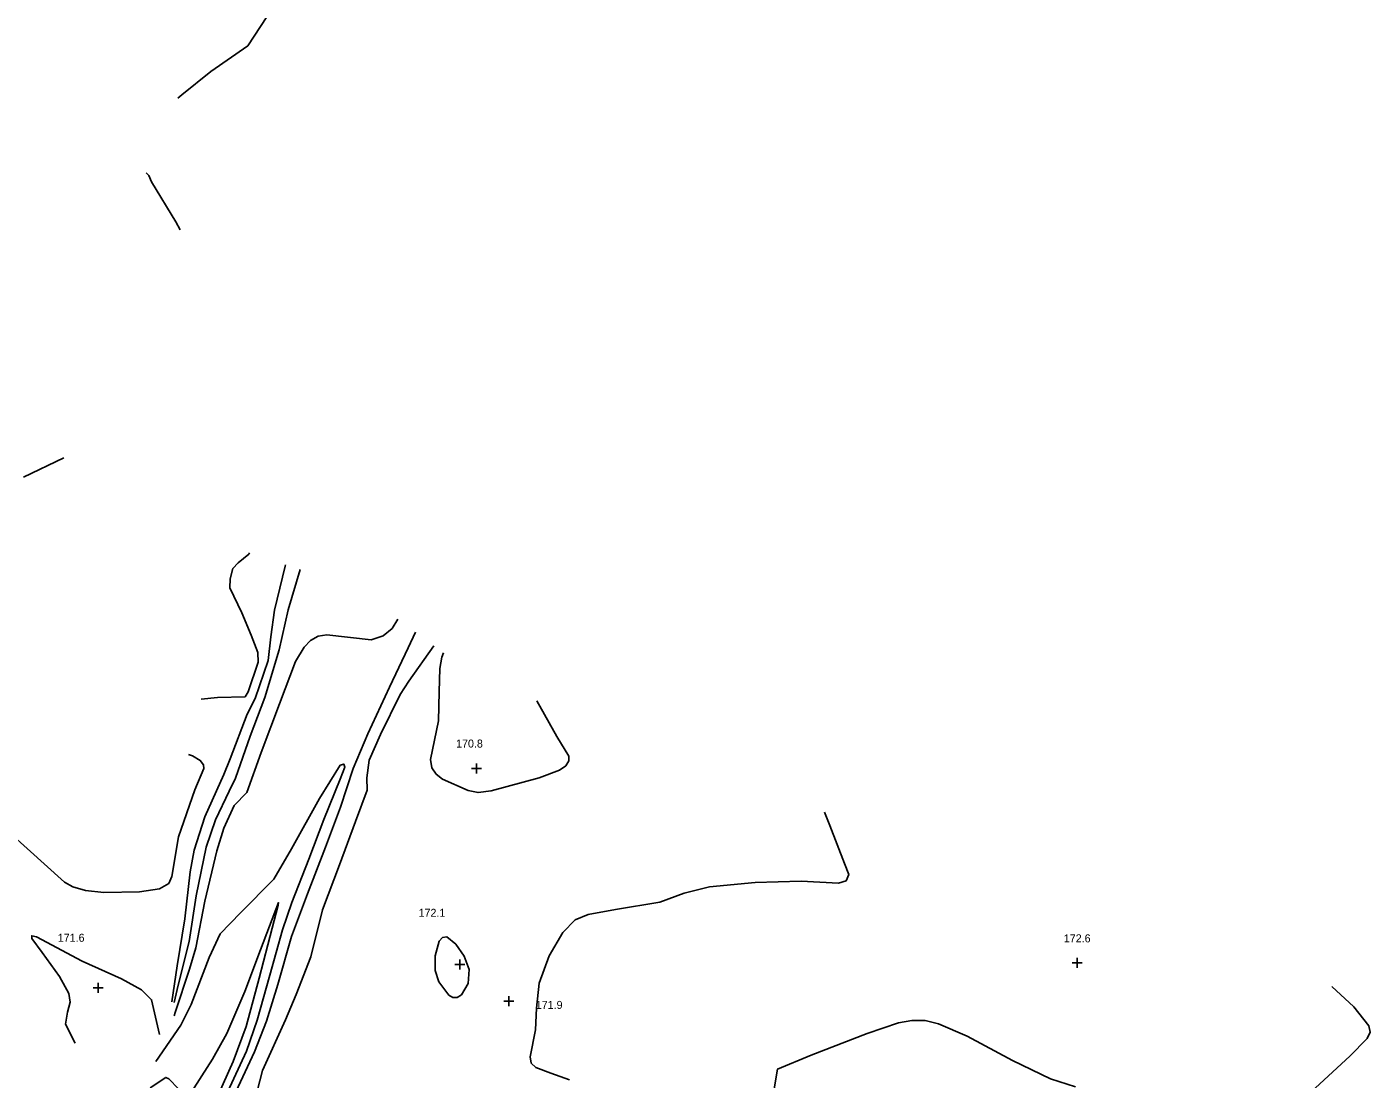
# Model space of a CAD drawing. Extents: x 1475150 to 2003689, y 770235 to 1112803.
# Drawn here: x 1996088.1 to 1996423.9, y 776721.2 to 776984.1 of the extents above; entities that cross this region are included whole.
import ezdxf

# ---------------------------------------------------------------- set-up
doc = ezdxf.new("R2010")
doc.units = 0
for name, color, linetype in [('RD_DTM_Major1', 7, 'Continuous'), ('RD_DTM_Minor1', 7, 'Continuous'), ('RD_DTM_Spot_Elev', 7, 'Continuous')]:
    doc.layers.add(name, color=color, linetype=linetype)

msp = doc.modelspace()

# ---------------------------------------------------------------- linework, layer by layer
at = {"layer": 'RD_DTM_Major1'}
for points in [[(1996124.95, 776736.99), (1996125.23, 776737.8), (1996128.77, 776748.7), (1996130.38, 776753.96), (1996132.66, 776765.67), (1996135.61, 776778.25), (1996137.35, 776783.88), (1996140, 776789.57), (1996143.16, 776792.78), (1996146.75, 776802.75), (1996151.3, 776814.95), (1996155.26, 776825.54), (1996157.48, 776829.09), (1996159.06, 776830.76), (1996160.95, 776831.86), (1996163.1, 776832.17), (1996174.21, 776830.92), (1996177.21, 776831.9), (1996179.42, 776833.8), (1996180.83, 776836.06)], [(1996185.27, 776832.84), (1996183.47, 776828.91), (1996178.75, 776819.1), (1996173.41, 776807.48), (1996169.69, 776798.82), (1996166.55, 776789.17), (1996162.82, 776779.11), (1996158.33, 776767.46), (1996154.26, 776756.8), (1996150.86, 776744.84), (1996148.03, 776735.68), (1996145.08, 776728.02), (1996139.23, 776715.48)]]:
    msp.add_lwpolyline(points, dxfattribs=at)
at = {"layer": 'RD_DTM_Minor1'}
for points in [[(1996125.92, 776966.23), (1996126.87, 776967.1), (1996134.13, 776972.88), (1996143.39, 776979.33), (1996149.73, 776989), (1996150.32, 776989.76)], [(1996126.44, 776933.36), (1996125.36, 776935.35), (1996119.34, 776945.39), (1996118.63, 776946.95), (1996117.97, 776947.56)], [(1996087.32, 776871.6), (1996097.4, 776876.38)], [(1996131.72, 776816.15), (1996135.8, 776816.53), (1996142.69, 776816.72), (1996143.49, 776817.93), (1996145.97, 776825.33), (1996145.88, 776827.76), (1996144.18, 776832.14), (1996141.87, 776837.68), (1996138.89, 776843.95), (1996138.96, 776846.14), (1996139.62, 776848.73), (1996140.93, 776850.2), (1996143.61, 776852.31), (1996143.77, 776852.66)], [(1996124.37, 776740.49), (1996125.72, 776749.46), (1996127.65, 776761.21), (1996128.98, 776772.99), (1996129.94, 776778.38), (1996132.63, 776786.7), (1996137.4, 776797.28), (1996138.96, 776801.19), (1996143.19, 776812.34), (1996145.23, 776816.24), (1996148.42, 776825.74), (1996149.1, 776831.72), (1996150.08, 776838.36), (1996152.75, 776849.37), (1996152.81, 776849.71)], [(1996124.94, 776740.3), (1996125.93, 776744.65), (1996128.73, 776755.54), (1996130.49, 776767.01), (1996132.98, 776779.1), (1996135.3, 776785.97), (1996138.69, 776793.09), (1996140.28, 776796.41), (1996143.96, 776806.88), (1996147.62, 776816.52), (1996151.2, 776828.41), (1996153.49, 776838.43), (1996156.47, 776848.51)], [(1996189.89, 776829.47), (1996183.59, 776820.59), (1996181.48, 776817.28), (1996176.57, 776807.31), (1996173.73, 776800.86), (1996173.13, 776796.45), (1996173.23, 776793.39), (1996170.28, 776785.59), (1996166.26, 776774.76), (1996162.02, 776763.49), (1996159.12, 776751.76), (1996155.5, 776742.36), (1996152.82, 776736), (1996147.04, 776723.35), (1996145.72, 776718.18)], [(1996215.65, 776815.68), (1996220.64, 776806.77), (1996223.65, 776801.84), (1996223.61, 776800.7), (1996222.87, 776799.47), (1996221.3, 776798.35), (1996216.21, 776796.48), (1996204.24, 776793.22), (1996200.92, 776792.77), (1996198.47, 776793.28), (1996192.06, 776796.16), (1996190.42, 776797.38), (1996189.35, 776798.98), (1996189.07, 776801.01), (1996190.01, 776805.87), (1996191.02, 776810.69), (1996191.19, 776817.94), (1996191.36, 776823.79), (1996191.85, 776826.57), (1996192.32, 776827.71)], [(1996079.63, 776786.45), (1996088.23, 776778.77), (1996097.58, 776770.43), (1996099.66, 776769.23), (1996102.83, 776768.35), (1996107.42, 776767.84), (1996116.26, 776767.96), (1996121.26, 776768.76), (1996123.64, 776770.09), (1996124.39, 776771.85), (1996126.07, 776781.73), (1996130.12, 776793.43), (1996132.38, 776798.77), (1996132.27, 776799.74), (1996131.48, 776800.83), (1996129.58, 776801.97), (1996128.56, 776802.27)], [(1996120.38, 776725.56), (1996126.63, 776734.65), (1996129.2, 776739.86), (1996133.68, 776751.6), (1996136.47, 776757.51), (1996141.54, 776762.7), (1996149.88, 776771.18), (1996154.26, 776778.71), (1996161.33, 776791.33), (1996166.48, 776799.6), (1996167.37, 776799.9), (1996167.59, 776799.13), (1996166.46, 776796.09), (1996162.41, 776786.09), (1996158.66, 776776.18), (1996154.34, 776765.34), (1996152.02, 776758.46), (1996148.91, 776747.12), (1996145.75, 776735.9), (1996143.05, 776728.21), (1996138.27, 776717.9)], [(1996287.53, 776787.88), (1996288.84, 776784.51), (1996292.51, 776775.05), (1996293.58, 776772.29), (1996292.9, 776770.76), (1996291.03, 776770.18), (1996281.72, 776770.65), (1996270.2, 776770.29), (1996258.78, 776769.22), (1996252.47, 776767.64), (1996246.33, 776765.38), (1996235.29, 776763.59), (1996228.44, 776762.33), (1996225.16, 776760.95), (1996222.12, 776757.81), (1996218.73, 776752.02), (1996216.19, 776745.14), (1996215.55, 776738.94), (1996215.32, 776733.51), (1996213.91, 776726.79), (1996214.22, 776725.21), (1996215.38, 776724.08), (1996219.15, 776722.72), (1996223.8, 776721.04)], [(1996128.63, 776716.9), (1996134.54, 776726.18), (1996138.17, 776732.56), (1996142.65, 776743.06), (1996146.52, 776753.46), (1996151.05, 776765.28), (1996150.96, 776764.66), (1996149.43, 776758.94), (1996146.23, 776746.43), (1996142.96, 776734.37), (1996139.71, 776725.58), (1996134.75, 776714.44)], [(1996100.21, 776730.18), (1996097.84, 776734.88), (1996098.28, 776737.89), (1996098.98, 776740.4), (1996098.61, 776742.55), (1996096.32, 776746.8), (1996091.95, 776752.79), (1996089.41, 776756.29), (1996089.37, 776757.02), (1996090.54, 776756.74), (1996101.95, 776750.68), (1996111.8, 776746.21), (1996116.78, 776743.49), (1996119.31, 776741.03), (1996121.33, 776732.33)], [(1996192.06, 776756.61), (1996191.21, 776755.63), (1996190.18, 776752.02), (1996190.17, 776748.31), (1996191.14, 776745.51), (1996193.64, 776742.16), (1996194.64, 776741.58), (1996195.69, 776741.58), (1996196.75, 776742.27), (1996198.45, 776745.11), (1996198.74, 776748.58), (1996197.48, 776751.87), (1996195.37, 776754.89), (1996193.08, 776756.71), (1996192.06, 776756.61)], [(1996414.35, 776744.3), (1996419.81, 776739.24), (1996423.61, 776734.5), (1996423.9, 776732.92), (1996423.16, 776731.37), (1996418.85, 776726.9), (1996409.14, 776717.99)], [(1996350.27, 776719.3), (1996344.01, 776721.24), (1996334.5, 776725.83), (1996323.16, 776731.94), (1996316.04, 776735.04), (1996312.66, 776735.81), (1996309.36, 776735.86), (1996305.98, 776735.28), (1996298.19, 776732.63), (1996284.15, 776727.17), (1996275.79, 776723.68), (1996274.47, 776715.78)], [(1996118.99, 776719.05), (1996122.88, 776721.62), (1996123.67, 776721.25), (1996126.03, 776718.74)]]:
    msp.add_lwpolyline(points, dxfattribs=at)
at = {"layer": 'RD_DTM_Spot_Elev'}
for p, q in [((1996200.57, 776797.55), (1996200.57, 776800.05)), ((1996199.32, 776798.8), (1996201.82, 776798.8)), ((1996195.08, 776749.81), (1996197.58, 776749.81)), ((1996196.33, 776748.56), (1996196.33, 776751.06)), ((1996349.45, 776750.25), (1996351.95, 776750.25)), ((1996350.7, 776749), (1996350.7, 776751.5)), ((1996104.7, 776744), (1996107.2, 776744)), ((1996105.95, 776742.75), (1996105.95, 776745.25)), ((1996207.36, 776740.7), (1996209.86, 776740.7)), ((1996208.61, 776739.45), (1996208.61, 776741.95))]:
    msp.add_line(p, q, dxfattribs=at)

# ---------------------------------------------------------------- texts
for s, p in [('170.8', (1996195.43, 776804.02)), ('172.1', (1996186.05, 776761.74)), ('171.6', (1996095.87, 776755.51)), ('172.6', (1996347.33, 776755.36)), ('171.9', (1996215.35, 776738.73))]:
    msp.add_text(s, height=2, dxfattribs=at).set_placement(p)

doc.saveas('drawing.dxf')
